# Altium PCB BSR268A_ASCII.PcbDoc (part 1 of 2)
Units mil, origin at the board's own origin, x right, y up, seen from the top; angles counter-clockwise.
Board outline 3689.1 x 2409.61 mil, 4 copper layers (Top Layer, Signal Layer 1, Signal Layer 2, Bottom Layer), stack 60.312 mil thick; 90 components, 29 nets, 160 pads, 335 vias.
Unrouted connection lines stored in the file: 5.
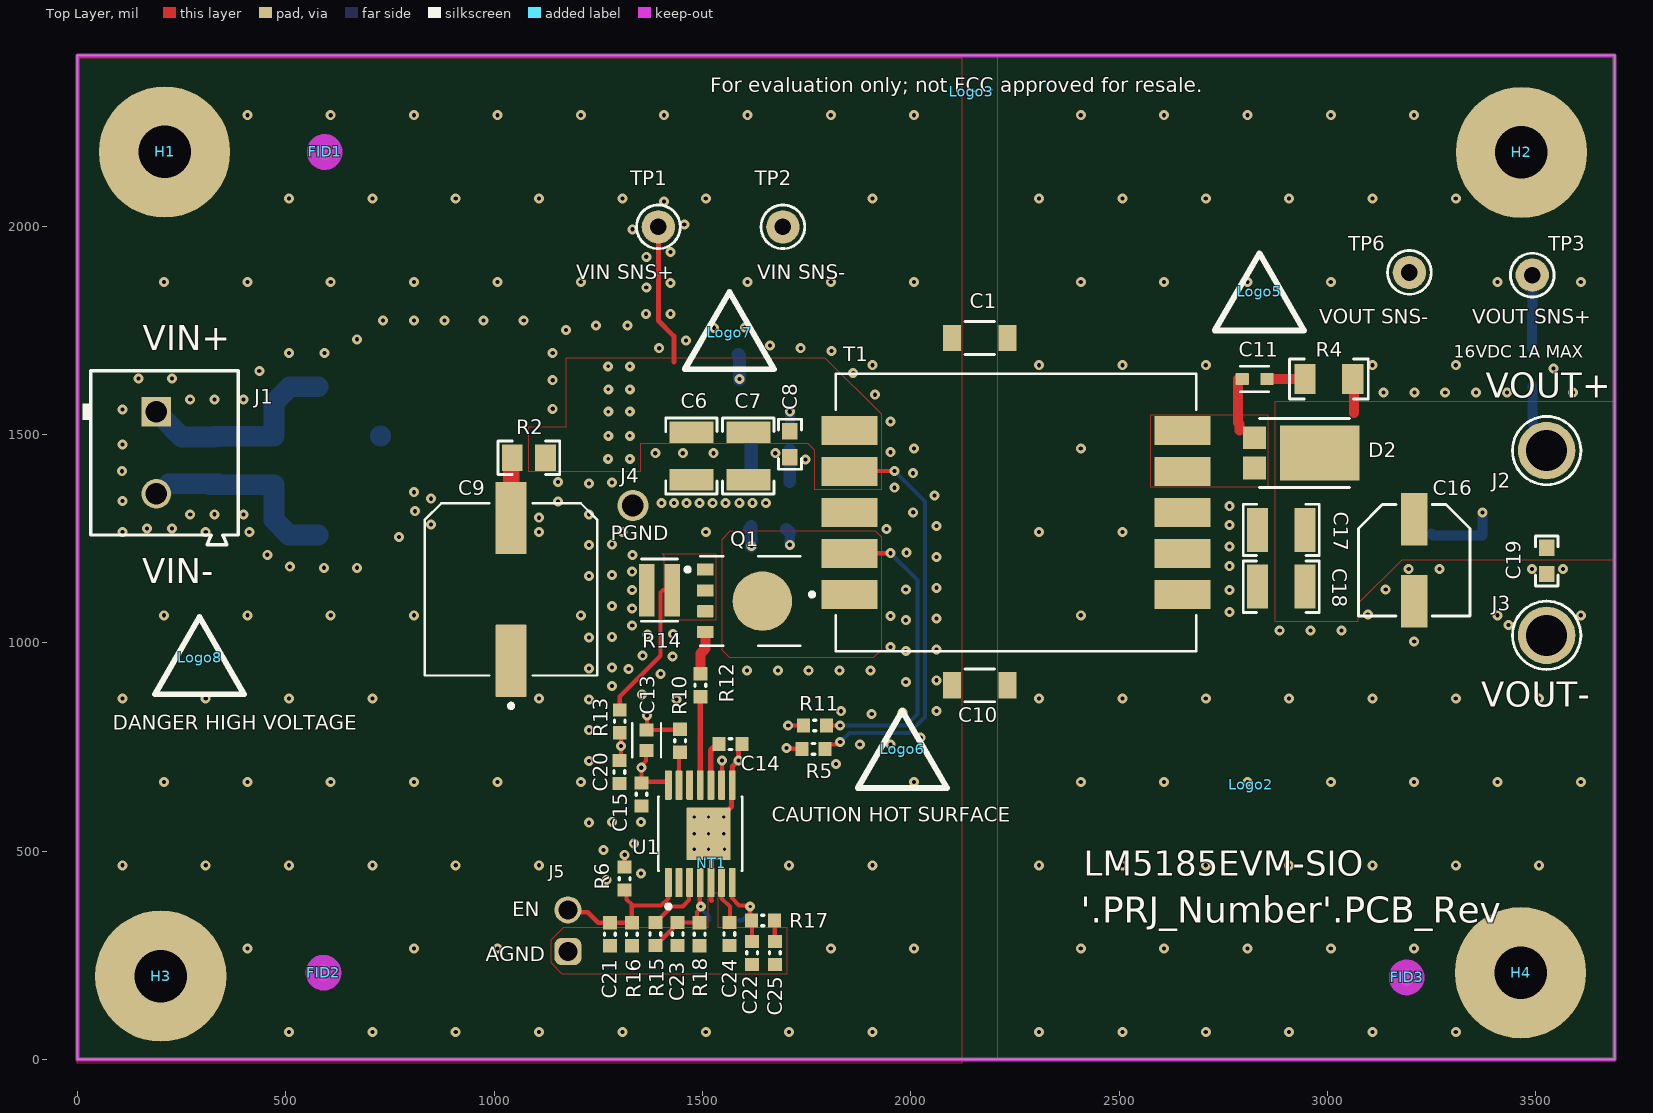
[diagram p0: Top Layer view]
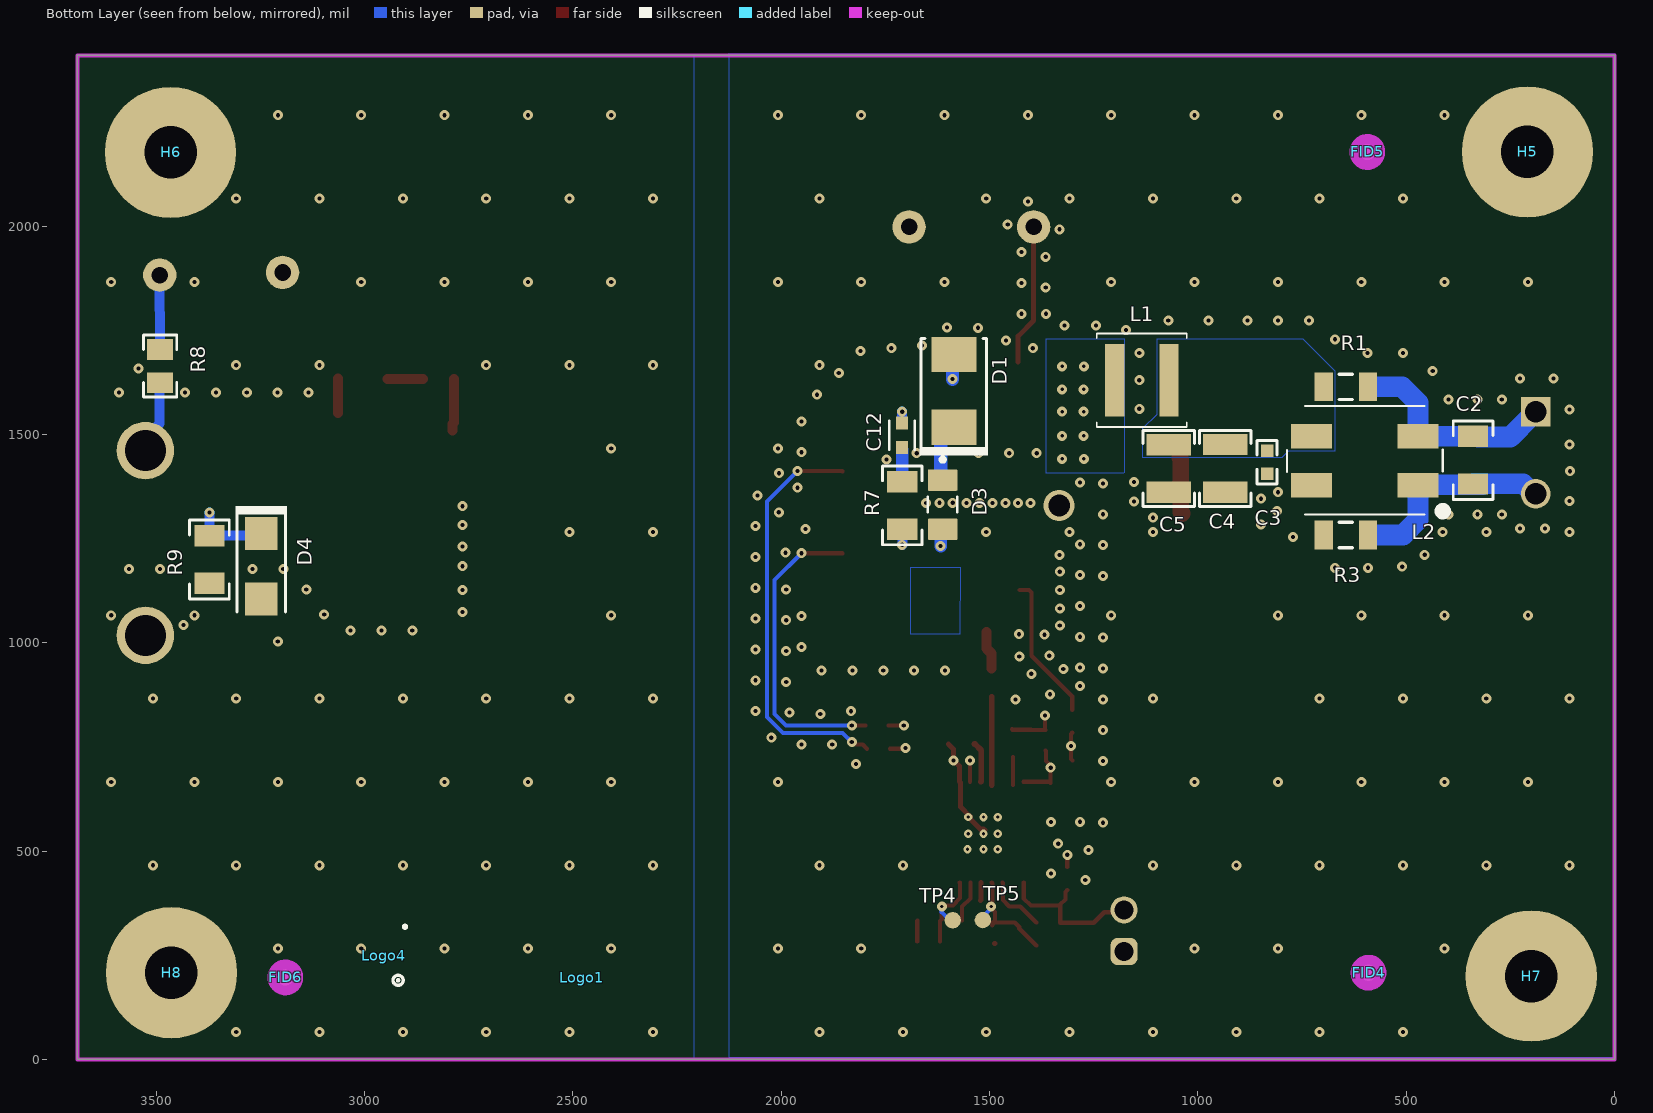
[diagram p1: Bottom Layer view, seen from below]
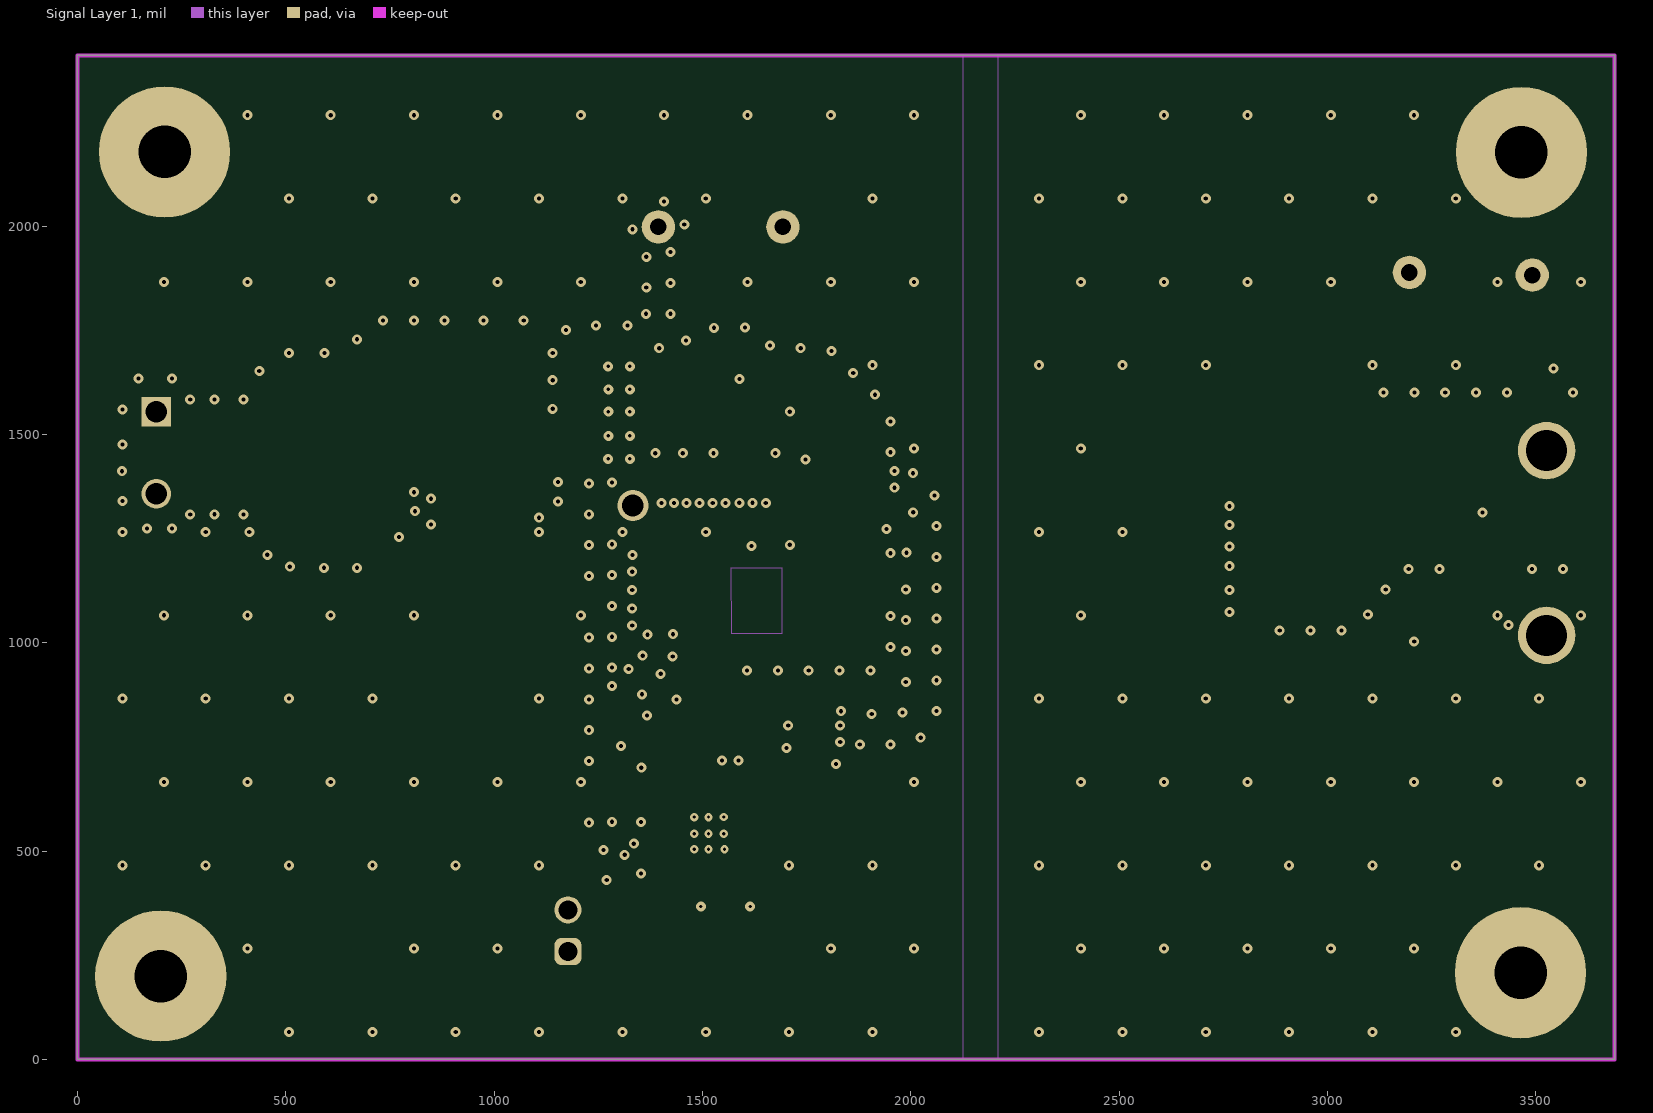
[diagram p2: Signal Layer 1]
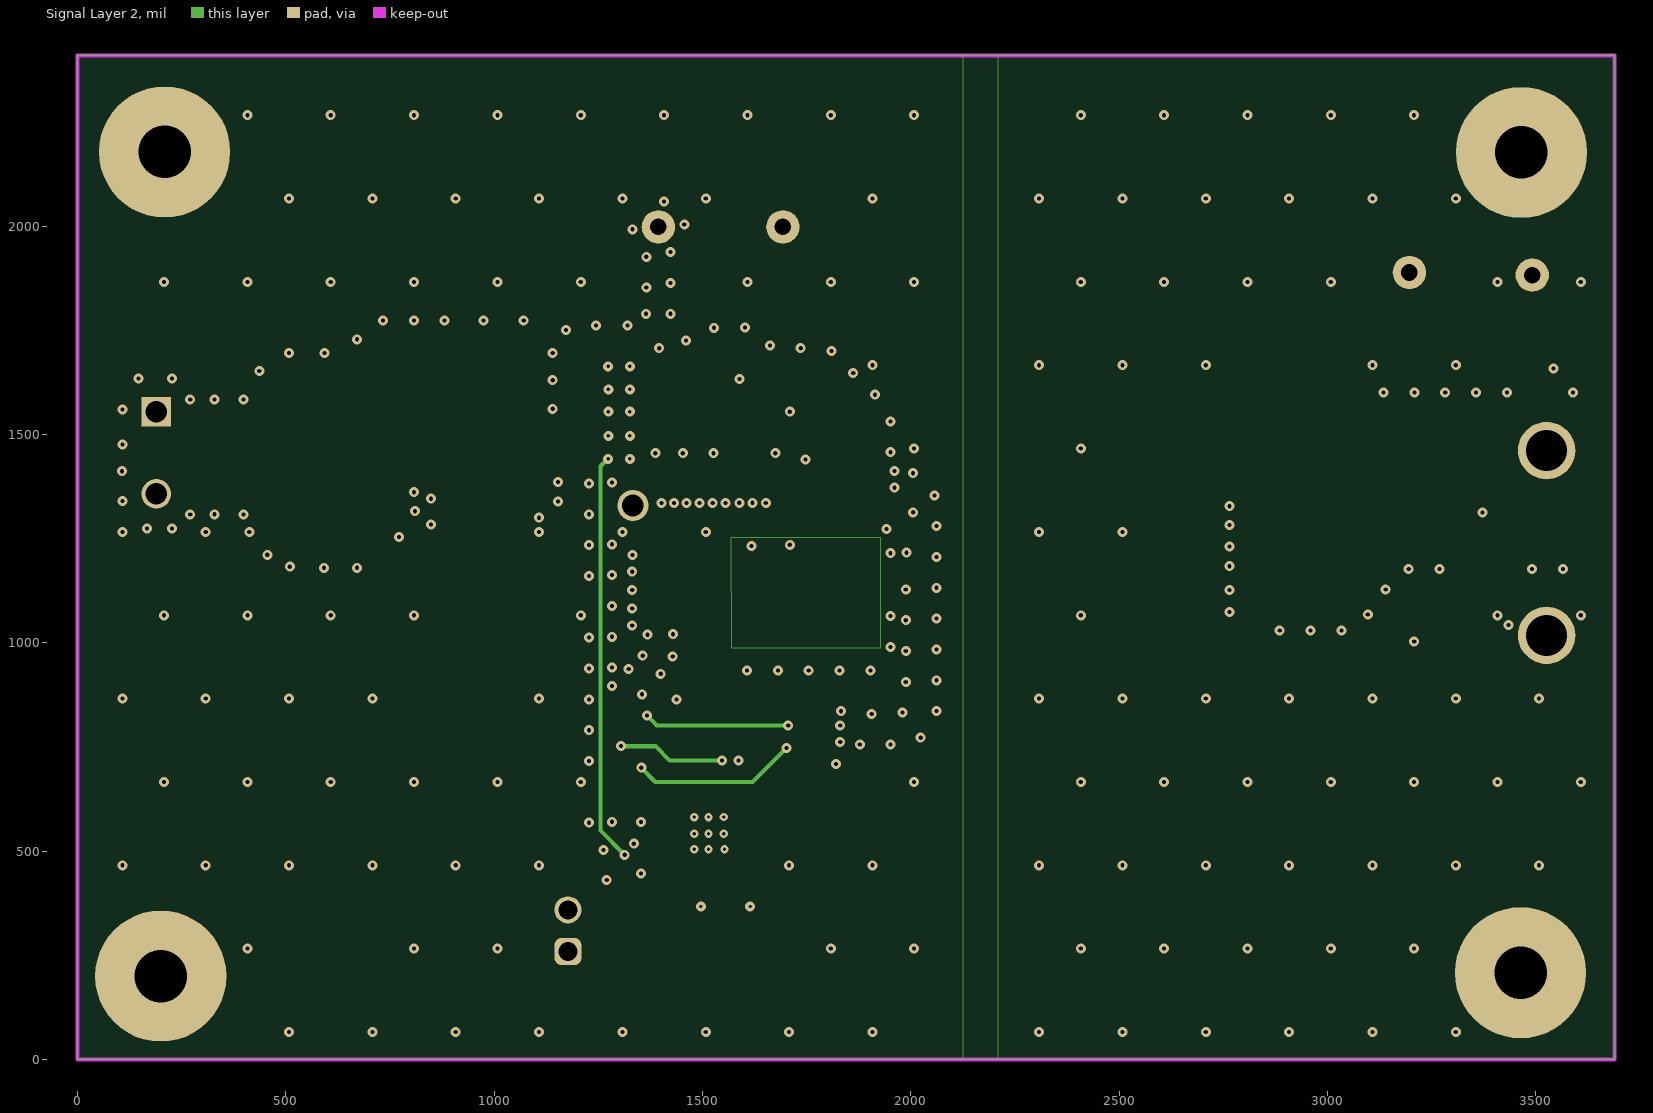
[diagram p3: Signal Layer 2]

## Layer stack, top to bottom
Top Solder: solder mask 0.4, Solder Resist, Dk 3.5
Top Layer: signal copper 2.7559
Dielectric 1: prepreg 8, FR-4 High Tg, Dk 4.1
Signal Layer 1: signal copper 1.4
Dielectric1: core 36, FR-4 High Tg, Dk 4.8
Signal Layer 2: signal copper 1.4
Dielectric 2: prepreg 8, FR-4 High Tg, Dk 4.1
Bottom Layer: signal copper 2.7559
Bottom Solder: solder mask 0.4, Solder Resist, Dk 3.5

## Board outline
0,0 3689.1,0 3689.1,2409.61 0,2409.61

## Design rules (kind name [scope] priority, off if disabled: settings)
AcuteAngle [All] p0: scope1count=1 scope1_0_kind=Board scope1_0_value=Board scope2count=1 scope2_0_kind=Board scope2_0_value=Board commentlength=0 minimum=4.50000000000000E+0001
AcuteAngle [All] p1: minimum=4.50000000000000E+0001 checktracksonly=FALSE
AssemblyTestPointUsage [All] p0: scope1count=1 scope1_0_kind=Board scope1_0_value=Board scope2count=1 scope2_0_kind=Board scope2_0_value=Board commentlength=0
AssemblyTestPointUsage [All] p1: valid=2
AssemblyTestpoint [All] p0: scope1count=1 scope1_0_kind=Board scope1_0_value=Board scope2count=1 scope2_0_kind=Board scope2_0_value=Board commentlength=0
BoardOutlineClearance [All] p0 off: scope1count=1 scope1_0_kind=Board scope1_0_value=Board scope2count=1 scope2_0_kind=Board scope2_0_value=Board commentlength=172 gap=40 // Protel DXP Scope 1 Expression Was: OnCopper and Not InComponentClass('Logo') and not InComponentClass('FiducialMark') and not InRegion(1000,500,4000,800) and not InPoly
BoardOutlineClearance BoardOutlineClearance_Poly [All] p0 off: scope1count=1 scope1_0_kind=Board scope1_0_value=Board scope2count=1 scope2_0_kind=Board scope2_0_value=Board commentlength=58 gap=25 // Protel DXP Scope 1 Expression Was: OnCopper and IsPoly
BoardOutlineClearance BoardOutlineClearance_MountingHoles [All] p0 off: scope1count=1 scope1_0_kind=Board scope1_0_value=Board scope2count=1 scope2_0_kind=Board scope2_0_value=Board commentlength=86 gap=39.37 // Protel DXP Scope 1 Expression Was: OnCopper and InComponentClass('Mounting Holes')
BoardOutlineClearance BoardOutlineClearance_MountingHoles [OnCopper and InComponentClass('Mounting Holes')] p1: gap=39.37 ignorepadtopadclearanceinfootprint=FALSE
BoardOutlineClearance BoardOutlineClearance_Poly [OnCopper and IsPoly] p2: gap=25 ignorepadtopadclearanceinfootprint=FALSE
BoardOutlineClearance [OnCopper and Not InComponentClass('Logo') and not InComponentClass('FiducialMark') and not InRegion(1000,500,4000,800) and not InPoly] p3: gap=40 ignorepadtopadclearanceinfootprint=FALSE
Clearance Clearance_VIN_EMI [All] p0: scope1count=1 scope1_0_kind=NetClass scope1_0_value=EMI_Net scope2count=1 scope2_0_kind=Board scope2_0_value=Board commentlength=0 gap=24
Clearance [All] p0: scope1count=1 scope1_0_kind=Board scope1_0_value=Board scope2count=1 scope2_0_kind=Board scope2_0_value=Board commentlength=0 gap=7.87
Clearance Clearance_FiducialMark [All] p0 off: scope1count=1 scope1_0_kind=Board scope1_0_value=Board scope2count=1 scope2_0_kind=Board scope2_0_value=Board commentlength=81 gap=0 // Protel DXP Scope 2 Expression Was: IsPad and InComponentClass('FiducialMark')
Clearance Clearance_Poly [All] p0 off: scope1count=1 scope1_0_kind=Board scope1_0_value=Board scope2count=1 scope2_0_kind=Board scope2_0_value=Board commentlength=48 gap=10 // Protel DXP Scope 1 Expression Was: InPolygon
Clearance Clearance_Keepouts [All] p0 off: scope1count=1 scope1_0_kind=Board scope1_0_value=Board scope2count=1 scope2_0_kind=Board scope2_0_value=Board commentlength=99 gap=0 // Protel DXP Scope 2 Expression Was: ((IsTrack Or IsArc) And Not InPoly) And IsFree and IsKeepOut
Clearance Clearance_Keepouts [((IsTrack Or IsArc) And Not InPoly) And IsFree and IsKeepOut vs ((IsTrack Or IsArc) And Not InPoly) And IsFree and IsKeepOut] p1: gap=0 ignorepadtopadclearanceinfootprint=FALSE
Clearance Clearance_VIN_EMI [InNetClass('EMI_Net')] p2: gap=24 ignorepadtopadclearanceinfootprint=FALSE
Clearance Clearance_Poly [InPolygon] p3: gap=10 ignorepadtopadclearanceinfootprint=TRUE
Clearance Clearance_FiducialMark [IsKeepOut and InComponentClass('FiducialMark') vs IsPad and InComponentClass('FiducialMark')] p4: gap=0 ignorepadtopadclearanceinfootprint=FALSE
Clearance [All] p5: gap=7.87 ignorepadtopadclearanceinfootprint=TRUE
ComponentClearance "ComponentClearance_CM Choke" [All] p0 off: scope1count=1 scope1_0_kind=Board scope1_0_value=Board scope2count=1 scope2_0_kind=Footprint scope2_0_value=IND_TDK_ACM7060 commentlength=79 gap=0 collisioncheckmode=3 // Protel DXP Scope 1 Expression Was: InComponent('R17') OR InComponent('R18')
ComponentClearance ComponentClearance_NetTie [All] p0: scope1count=1 scope1_0_kind=Footprint scope1_0_value=Net-Tie_10milWide_30milLong scope2count=1 scope2_0_kind=Board scope2_0_value=Board commentlength=0 gap=0 collisioncheckmode=3
ComponentClearance [All] p0: scope1count=1 scope1_0_kind=Board scope1_0_value=Board scope2count=1 scope2_0_kind=Board scope2_0_value=Board commentlength=0 gap=15 collisioncheckmode=3
ComponentClearance ComponentClearance_THtoTH [All] p0 off: scope1count=1 scope1_0_kind=Board scope1_0_value=Board scope2count=1 scope2_0_kind=Board scope2_0_value=Board commentlength=54 gap=20 collisioncheckmode=3 // Protel DXP Scope 2 Expression Was: IsThruComponent
ComponentClearance ComponentClearance_THtoSMT [All] p0 off: scope1count=1 scope1_0_kind=Board scope1_0_value=Board scope2count=1 scope2_0_kind=Board scope2_0_value=Board commentlength=53 gap=30 collisioncheckmode=3 // Protel DXP Scope 2 Expression Was: IsSMTComponent
ComponentClearance ComponentClearance_SmallPassives [All] p0 off: scope1count=1 scope1_0_kind=Board scope1_0_value=Board scope2count=1 scope2_0_kind=Board scope2_0_value=Board commentlength=508 gap=14.96 collisioncheckmode=3 // Protel DXP Scope 2 Expression Was: HasFootprint('0201*') or HasFootprint('0402*') or HasFootprint('0508') or HasFootprint('0603*') or HasFootprint('0612') or HasFootprint('0805*') or HasFootprint('0815*') or HasFootprint('0830*') or HasFootprint('1206*') or HasFootprint('1210*') or HasFootprint('1808*') or HasFootprint('1812*') or HasFootprint('1825*') or HasFootprint('2010*') or HasFootprint('2220*') or HasFootprint('2225*') or HasFootprint('2512*') or HasFootprint('2728*') or HasFootprint('3518*')
ComponentClearance ComponentClearance_MountingHoles [All] p0: scope1count=1 scope1_0_kind=ComponentClass scope1_0_value="Mounting Holes" scope2count=1 scope2_0_kind=Board scope2_0_value=Board commentlength=0 gap=100 collisioncheckmode=3
ComponentClearance ComponentClearance_ScrewToNut [All] p0 off: scope1count=1 scope1_0_kind=Board scope1_0_value=Board scope2count=1 scope2_0_kind=Board scope2_0_value=Board commentlength=71 gap=5 collisioncheckmode=3 // Protel DXP Scope 2 Expression Was: (HasFootprint('Keystone_1902C'))
ComponentClearance ComponentClearance_Logo [All] p0: scope1count=1 scope1_0_kind=ComponentClass scope1_0_value=Logo scope2count=1 scope2_0_kind=Board scope2_0_value=Board commentlength=0 gap=30 collisioncheckmode=3
ComponentClearance ComponentClearance_Shunt [All] p0: scope1count=1 scope1_0_kind=ComponentClass scope1_0_value=Header scope2count=1 scope2_0_kind=ComponentClass scope2_0_value=Shunt commentlength=0 gap=0 collisioncheckmode=3
ComponentClearance ComponentClearance_MountingHoles_FiducialMarks [All] p0: scope1count=1 scope1_0_kind=ComponentClass scope1_0_value="Mounting Holes" scope2count=1 scope2_0_kind=ComponentClass scope2_0_value=FiducialMark commentlength=0 gap=50 collisioncheckmode=3
ComponentClearance ComponentClearance_MountingHoles_FiducialMarks [InComponentClass('Mounting Holes') vs InComponentClass('FiducialMark')] p1: gap=50 collisioncheckmode=3 verticalgap=10 showdistances=FALSE
ComponentClearance ComponentClearance_Shunt [InComponentClass('Header') vs InComponentClass('Shunt')] p2: gap=0 collisioncheckmode=3 verticalgap=0 showdistances=FALSE
ComponentClearance ComponentClearance_Logo [InComponentClass('Logo')] p3: gap=30 collisioncheckmode=3 verticalgap=10 showdistances=FALSE
ComponentClearance ComponentClearance_ScrewToNut [(HasFootprint('NY PMS 440 0025 PH')) vs (HasFootprint('Keystone_1902C'))] p4: gap=5 collisioncheckmode=3 verticalgap=10 showdistances=FALSE
ComponentClearance ComponentClearance_MountingHoles [InComponentClass('Mounting Holes')] p5: gap=100 collisioncheckmode=3 verticalgap=100000 showdistances=FALSE
ComponentClearance ComponentClearance_SmallPassives [HasFootprint('0201*') or HasFootprint('0402*') or HasFootprint('0508') or HasFootprint('0603*') or HasFootprint('0612') or HasFootprint('0805*') or HasFootprint('0815*') or HasFootprint('0830*') or HasFootprint('1206*') or HasFootprint('1210*') or HasFootprint('1808*') or HasFootprint('1812*') or HasFootprint('1825*') or HasFootprint('2010*') or HasFootprint('2220*') or HasFootprint('2225*') or HasFootprint('2512*') or HasFootprint('2728*') or HasFootprint('3518*') vs HasFootprint('0201*') or HasFootprint('0402*') or HasFootprint('0508') or HasFootprint('0603*') or HasFootprint('0612') or HasFootprint('0805*') or HasFootprint('0815*') or HasFootprint('0830*') or HasFootprint('1206*') or HasFootprint('1210*') or HasFootprint('1808*') or HasFootprint('1812*') or HasFootprint('1825*') or HasFootprint('2010*') or HasFootprint('2220*') or HasFootprint('2225*') or HasFootprint('2512*') or HasFootprint('2728*') or HasFootprint('3518*')] p6: gap=14.96 collisioncheckmode=3 verticalgap=10 showdistances=FALSE
ComponentClearance ComponentClearance_THtoSMT [IsThruComponent vs IsSMTComponent] p7: gap=30 collisioncheckmode=3 verticalgap=30 showdistances=FALSE
ComponentClearance ComponentClearance_THtoTH [IsThruComponent vs IsThruComponent] p8: gap=20 collisioncheckmode=3 verticalgap=30 showdistances=FALSE
ComponentClearance ComponentClearance_NetTie [HasFootprint('Net-Tie_10milWide_30milLong')] p9: gap=0 collisioncheckmode=3 verticalgap=0 showdistances=FALSE
ComponentClearance "ComponentClearance_CM Choke" [InComponent('R17') OR InComponent('R18') vs HasFootprint('IND_TDK_ACM7060')] p10: gap=0 collisioncheckmode=3 verticalgap=0 showdistances=FALSE
ComponentClearance [All] p11: gap=15 collisioncheckmode=3 verticalgap=10 showdistances=FALSE
DiffPairsRouting [All] p0: scope1count=1 scope1_0_kind=Board scope1_0_value=Board scope2count=1 scope2_0_kind=Board scope2_0_value=Board commentlength=0
DiffPairsRouting [All] p1: maxlimit=100 minlimit=10 mostfreqgap=10 toplayer_minwidth=15 toplayer_maxwidth=15 toplayer_prefwidth=15 midlayer1_minwidth=15 midlayer1_maxwidth=15 midlayer1_prefwidth=15 midlayer2_minwidth=15 midlayer2_maxwidth=15 midlayer2_prefwidth=15 bottomlayer_minwidth=15 bottomlayer_maxwidth=15 bottomlayer_prefwidth=15 maxuncoupledlength=1000
FabricationTestPointUsage TestPointUsage [All] p0: scope1count=1 scope1_0_kind=Board scope1_0_value=Board scope2count=1 scope2_0_kind=Board scope2_0_value=Board commentlength=0 valid=2 allowmultiple=FALSE
FabricationTestPointUsage TestPointUsage [All] p1: valid=2 allowmultiple=FALSE
FabricationTestpoint Testpoint [All] p0: scope1count=1 scope1_0_kind=Board scope1_0_value=Board scope2count=1 scope2_0_kind=Board scope2_0_value=Board commentlength=0 side=3 testpointundercomponent=TRUE minsize=40 maxsize=100 preferedsize=60 minholesize=0 maxholesize=40 preferedholesize=32 testpointgrid=1
FabricationTestpoint Testpoint [All] p1: side=3 testpointundercomponent=TRUE minsize=40 maxsize=100 preferedsize=60 minholesize=0 maxholesize=40 preferedholesize=32 testpointgrid=1 allowsidetop=TRUE allowsidebottom=TRUE usegrid=TRUE gridtolerance=0.01
FanoutControl Fanout_Small [All] p0 off: scope1count=1 scope1_0_kind=Board scope1_0_value=Board scope2count=1 scope2_0_kind=Board scope2_0_value=Board commentlength=84 // Protel DXP Scope 1 Expression Was: (CompPinCount < 5)   Fanout_Small (Default Rule)
FanoutControl Fanout_Default [All] p0: scope1count=1 scope1_0_kind=Board scope1_0_value=Board scope2count=1 scope2_0_kind=Board scope2_0_value=Board commentlength=30 // Fanout_Default (Default Rule)
FanoutControl Fanout_SOIC [All] p0 off: scope1count=1 scope1_0_kind=Board scope1_0_value=Board scope2count=1 scope2_0_kind=Board scope2_0_value=Board commentlength=71 // Protel DXP Scope 1 Expression Was: IsSOIC   Fanout_SOIC (Default Rule)
FanoutControl Fanout_BGA [All] p0 off: scope1count=1 scope1_0_kind=Board scope1_0_value=Board scope2count=1 scope2_0_kind=Board scope2_0_value=Board commentlength=69 // Protel DXP Scope 1 Expression Was: IsBGA   Fanout_BGA (Default Rule)
FanoutControl Fanout_LCC [All] p0 off: scope1count=1 scope1_0_kind=Board scope1_0_value=Board scope2count=1 scope2_0_kind=Board scope2_0_value=Board commentlength=69 // Protel DXP Scope 1 Expression Was: IsLCC   Fanout_LCC (Default Rule)
FanoutControl Fanout_LCC [IsLCC] p1: bgadir=Out bgaviamode=Centered fanoutstyle=Auto fanoutdirection=Alternating viagrid=1 // Fanout_LCC (Default Rule)
FanoutControl Fanout_BGA [IsBGA] p2: bgadir=Out bgaviamode=Centered fanoutstyle=Auto fanoutdirection=Alternating viagrid=1 // Fanout_BGA (Default Rule)
FanoutControl Fanout_Default [All] p4: bgadir=Out bgaviamode=Centered fanoutstyle=Auto fanoutdirection=Alternating viagrid=1 // Fanout_Default (Default Rule)
FanoutControl Fanout_Small [(CompPinCount < 5)] p5: bgadir=Out bgaviamode=Centered fanoutstyle=Auto fanoutdirection=OutThenIn viagrid=1 // Fanout_Small (Default Rule)
Height [All] p0: scope1count=1 scope1_0_kind=Board scope1_0_value=Board scope2count=1 scope2_0_kind=Board scope2_0_value=Board commentlength=0
HoleSize [All] p0: scope1count=1 scope1_0_kind=Board scope1_0_value=Board scope2count=1 scope2_0_kind=Board scope2_0_value=Board commentlength=0 absolutevalues=TRUE maxlimit=251 minlimit=7.87 maxpercent=80.000 minpercent=20.000
HoleSize [All] p1: absolutevalues=TRUE maxlimit=251 minlimit=7.87 maxpercent=80.000 minpercent=20.000
HoleToHoleClearance [All] p0: scope1count=1 scope1_0_kind=Board scope1_0_value=Board scope2count=1 scope2_0_kind=Board scope2_0_value=Board commentlength=0
LayerPairs [All] p0: scope1count=1 scope1_0_kind=Board scope1_0_value=Board scope2count=1 scope2_0_kind=Board scope2_0_value=Board commentlength=0 enforce=TRUE
MinimumAnnularRing [All] p0: scope1count=1 scope1_0_kind=Board scope1_0_value=Board scope2count=1 scope2_0_kind=Board scope2_0_value=Board commentlength=0 minimumring=6
MinimumAnnularRing MinimumAnnularRing_ThermalPadVias [All] p0 off: scope1count=1 scope1_0_kind=Board scope1_0_value=Board scope2count=1 scope2_0_kind=Board scope2_0_value=Board commentlength=63 minimumring=5.91 // Protel DXP Scope 1 Expression Was: IsVia and InAnyComponent
MinimumAnnularRing MinimumAnnularRing_ThermalPadVias [IsVia and InAnyComponent] p1: minimumring=5.91
MinimumAnnularRing [All] p2: minimumring=6
MinimumSolderMaskSliver [All] p0: scope1count=1 scope1_0_kind=Board scope1_0_value=Board scope2count=1 scope2_0_kind=Board scope2_0_value=Board commentlength=0
MinimumSolderMaskSliver MinimumSolderMaskSliver_Logo [All] p0: scope1count=1 scope1_0_kind=ComponentClass scope1_0_value=Logo scope2count=1 scope2_0_kind=ComponentClass scope2_0_value=Logo commentlength=0
MinimumSolderMaskSliver MinimumSolderMaskSliver_Logo [InComponentClass('Logo') vs InComponentClass('Logo')] p1: minsoldermaskwidth=0.7
MinimumSolderMaskSliver [All] p2: minsoldermaskwidth=3.94
NetAntennae [All] p0: scope1count=1 scope1_0_kind=Board scope1_0_value=Board scope2count=1 scope2_0_kind=Board scope2_0_value=Board commentlength=0
PasteMaskExpansion [All] p0: scope1count=1 scope1_0_kind=Board scope1_0_value=Board scope2count=1 scope2_0_kind=Board scope2_0_value=Board commentlength=0 expansion=0
PlaneClearance [All] p0: scope1count=1 scope1_0_kind=Board scope1_0_value=Board scope2count=1 scope2_0_kind=Board scope2_0_value=Board commentlength=0 clearance=20
PlaneConnect [All] p0: scope1count=1 scope1_0_kind=Board scope1_0_value=Board scope2count=1 scope2_0_kind=Board scope2_0_value=Board commentlength=0 planeconnectstyle=Relief reliefexpansion=10 reliefentries=4 reliefconductorwidth=10 reliefairgap=10
PlaneConnect [All] p1: planeconnectstyle=Relief reliefexpansion=10 reliefentries=4 reliefconductorwidth=10 reliefairgap=10
PolygonConnect [All] p0: scope1count=1 scope1_0_kind=Board scope1_0_value=Board scope2count=1 scope2_0_kind=Board scope2_0_value=Board commentlength=0 connectstyle=Direct reliefconductorwidth=10 reliefentries=4 polygonreliefangle="90 Angle"
PolygonConnect [All] p1: connectstyle=Direct reliefconductorwidth=10 reliefentries=4 polygonreliefangle="90 Angle" airgapwidth=10
RoutingCorners [All] p0: scope1count=1 scope1_0_kind=Board scope1_0_value=Board scope2count=1 scope2_0_kind=Board scope2_0_value=Board commentlength=0 cornerstyle=45-Degree minsetback=100 maxsetback=100
RoutingLayers [All] p0: scope1count=1 scope1_0_kind=Board scope1_0_value=Board scope2count=1 scope2_0_kind=Board scope2_0_value=Board commentlength=0 top layer=Automatic mid layer 1=Automatic mid layer 2=Automatic bottom layer=Automatic
RoutingPriority [All] p0: scope1count=1 scope1_0_kind=Board scope1_0_value=Board scope2count=1 scope2_0_kind=Board scope2_0_value=Board commentlength=0
RoutingTopology [All] p0: scope1count=1 scope1_0_kind=Board scope1_0_value=Board scope2count=1 scope2_0_kind=Board scope2_0_value=Board commentlength=0 topology=Shortest
RoutingVias [All] p0: scope1count=1 scope1_0_kind=Board scope1_0_value=Board scope2count=1 scope2_0_kind=Board scope2_0_value=Board commentlength=0 holewidth=16 width=34 viastyle="Through Hole" minholewidth=7.87 minwidth=20 maxholewidth=40 maxwidth=65
RoutingVias ThermalPadVias [All] p0 off: scope1count=1 scope1_0_kind=Board scope1_0_value=Board scope2count=1 scope2_0_kind=Board scope2_0_value=Board commentlength=63 holewidth=7.87 width=19.68 viastyle="Through Hole" minholewidth=7.87 minwidth=19.68 maxholewidth=12.99 maxwidth=23.62 // Protel DXP Scope 1 Expression Was: IsVia and InAnyComponent
RoutingVias ThermalPadVias [IsVia and InAnyComponent] p1: holewidth=7.87 width=19.68 viastyle="Through Hole" minholewidth=7.87 minwidth=19.68 maxholewidth=12.99 maxwidth=23.62
RoutingVias [All] p2: holewidth=16 width=34 viastyle="Through Hole" minholewidth=7.87 minwidth=20 maxholewidth=40 maxwidth=65
ShortCircuit [All] p0: scope1count=1 scope1_0_kind=Board scope1_0_value=Board scope2count=1 scope2_0_kind=Board scope2_0_value=Board commentlength=0 allowed=FALSE
SilkToBoardRegionClearance [All] p0 off: scope1count=1 scope1_0_kind=Board scope1_0_value=Board scope2count=1 scope2_0_kind=Board scope2_0_value=Board commentlength=130 // Protel DXP Scope 1 Expression Was: Not ((IsComment or IsDesignator) And (Hide <> 'False')) and not InRegion(1000,500,4000,800)
SilkToBoardRegionClearance [Not ((IsComment or IsDesignator) And (Hide <> 'False')) and not InRegion(1000,500,4000,800)] p1:
SilkToSilkClearance [All] p0: scope1count=1 scope1_0_kind=Board scope1_0_value=Board scope2count=1 scope2_0_kind=Board scope2_0_value=Board commentlength=0
SilkToSilkClearance SilkToSilkClearance_Pb-FreeLogo [All] p0 off: scope1count=1 scope1_0_kind=Board scope1_0_value=Board scope2count=1 scope2_0_kind=Board scope2_0_value=Board commentlength=120 // Protel DXP Scope 2 Expression Was: (HasFootprint('Pb-Free_Overlay_Medium') OR HasFootprint('Pb-Free_Overlay_Small'))
SilkToSilkClearance SilkToSilkClearance_Pb-FreeLogo [(HasFootprint('Pb-Free_Overlay_Medium') OR HasFootprint('Pb-Free_Overlay_Small')) vs (HasFootprint('Pb-Free_Overlay_Medium') OR HasFootprint('Pb-Free_Overlay_Small'))] p1: silktosilkclearance=0
SilkToSilkClearance [All] p2: silktosilkclearance=3.94
SilkToSolderMaskClearance "Silk to Solder Mask Opening_TSSOP16" [All] p0: scope1count=1 scope1_0_kind=Footprint scope1_0_value=PWP0016A_N scope2count=1 scope2_0_kind=Board scope2_0_value=Board commentlength=0
SilkToSolderMaskClearance SilkToComponentPadClearance_TSSOP16 [All] p0 off: scope1count=1 scope1_0_kind=Board scope1_0_value=Board scope2count=1 scope2_0_kind=Board scope2_0_value=Board commentlength=100 // Protel DXP Scope 1 Expression Was: (IsPad or IsFill or IsRegion) and  HasFootprint('PWP0016A_N')
SilkToSolderMaskClearance SilkToComponentPadClearance_SOD123 [All] p0 off: scope1count=1 scope1_0_kind=Board scope1_0_value=Board scope2count=1 scope2_0_kind=Board scope2_0_value=Board commentlength=124 // Protel DXP Scope 1 Expression Was: (IsPad or IsFill or IsRegion) and HasFootprint('SOD-123') OR HasFootprint('SOD-123W')
SilkToSolderMaskClearance "Silk to Solder Mask Opening" [All] p0: scope1count=1 scope1_0_kind=Board scope1_0_value=Board scope2count=1 scope2_0_kind=Board scope2_0_value=Board commentlength=0
SilkToSolderMaskClearance SilkToComponentPadClearance [All] p0 off: scope1count=1 scope1_0_kind=Board scope1_0_value=Board scope2count=1 scope2_0_kind=Board scope2_0_value=Board commentlength=87 // Protel DXP Scope 1 Expression Was: (IsPad or IsFill or IsRegion) and InAnycomponent
SilkToSolderMaskClearance SilkToComponentPadClearance_TSSOP16 [(IsPad or IsFill or IsRegion) and  HasFootprint('PWP0016A_N')] p1: minsilkscreentomaskgap=0 clearancetoexposedcopper=TRUE
SilkToSolderMaskClearance SilkToComponentPadClearance_SOD123 [(IsPad or IsFill or IsRegion) and HasFootprint('SOD-123') OR HasFootprint('SOD-123W')] p2: minsilkscreentomaskgap=3 clearancetoexposedcopper=TRUE
SilkToSolderMaskClearance SilkToComponentPadClearance [(IsPad or IsFill or IsRegion) and InAnycomponent] p3: minsilkscreentomaskgap=5 clearancetoexposedcopper=TRUE
SilkToSolderMaskClearance "Silk to Solder Mask Opening_TSSOP16" [HasFootprint('PWP0016A_N')] p4: minsilkscreentomaskgap=0 clearancetoexposedcopper=FALSE
SilkToSolderMaskClearance "Silk to Solder Mask Opening" [All] p5: minsilkscreentomaskgap=3.94 clearancetoexposedcopper=FALSE
SolderMaskExpansion [All] p0: scope1count=1 scope1_0_kind=Board scope1_0_value=Board scope2count=1 scope2_0_kind=Board scope2_0_value=Board commentlength=0 expansion=1.97
SolderMaskExpansion [All] p1: expansion=1.97 istentingtop=FALSE
UnRoutedNet [All] p0: scope1count=1 scope1_0_kind=Board scope1_0_value=Board scope2count=1 scope2_0_kind=Board scope2_0_value=Board commentlength=0
UnRoutedNet [All] p1: checkbadconnections=TRUE
UnpouredPolygon [All] p0: scope1count=1 scope1_0_kind=Board scope1_0_value=Board scope2count=1 scope2_0_kind=Board scope2_0_value=Board commentlength=0
Width [All] p0: scope1count=1 scope1_0_kind=Board scope1_0_value=Board scope2count=1 scope2_0_kind=Board scope2_0_value=Board commentlength=0 maxlimit=100 minlimit=6 preferedwidth=10
Width [All] p1: maxlimit=100 minlimit=6 preferedwidth=10 checkconnectedcopper=TRUE
14 further rules are at their usual default settings.

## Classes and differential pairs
component class Header: J5
net class EMI_Net: NetC2_2 NetC3_1 VIN_EMI
component class "Mounting Holes": H1 H2 H3 H4
component class Logo: Logo2
component class FiducialMark: FID1 FID2 FID3 FID4 FID5 FID6
component class BSR268A_Hardware: !PCB1 FID1 FID2 FID3 FID4 FID5 FID6 H1 H2 H3 H4 H5 H6 H7 H8 Logo1 Logo2 Logo3 Logo4 Logo5 Logo6 Logo7 Logo8 ZZ1 ZZ2 ZZ3 ZZ4
component class AssemblyNote: ZZ1 ZZ2 ZZ3 ZZ4
component class BSR268A_BlankSheet: C1 C2 C3 C4 C5 C6 C7 C8 C9 C10 C11 C12 C13 C14 C15 C16 C17 C18 C19 C20 C21 C22 C23 C24 C25 D1 D2 D3 D4 J1 J2 J3 J4 J5 L1 L2 NT1 Q1 R1 R2 R3 R4 R5 R6 R7 R8 R9 R10 R11 R12 R13 R14 R15 R16 R17 R18 T1 TP1 TP2 TP3 TP4 TP5 TP6 U1

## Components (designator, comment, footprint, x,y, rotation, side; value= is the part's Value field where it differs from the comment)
C1 "202R18W102KV4E" 1206_190 2165.35,1731.3 r180 top
C2 "GRM319R72A104KA01D" 1206 339.68,1438.21 r270 bottom
C3 "GRM188R72A104KA35D" 0603_HV 833.91,1433.34 r270 bottom
C4 "C3225X7S2A475K200AB" 1210_220 934.52,1418.59 r270 bottom
C5 "C3225X7S2A475K200AB" 1210_220 1070.02,1418.47 r270 bottom
C6 "C3225X7S2A475K200AB" 1210_220 1473.69,1447.91 r270 top
C7 "C3225X7S2A475K200AB" 1210_220 1610.38,1447.91 r270 top
C8 "GRM188R72A104KA35D" 0603 1710.03,1476.4 r270 top
C9 "865081757008" FP-865081757008_SMT_CAP_10MM3_10MM3-MFG 1040.7,1128.17 r90 top
C10 "202R18W102KV4E" 1206_190 2165.35,898.01 r180 top
C11 "06031A151JAT2A" FP-06031A151JAT2A_0603-MFG 2825.02,1632.87 r0 top
C12 "06031A151JAT2A" FP-06031A151JAT2A_0603-MFG 1709.93,1498.05 r90 bottom
C13 "06031A101K4T2A" FP-06031A101K4T2A_0603-IPC_C 1365.93,766.18 r270 top
C14 "GRM188Z71C475KE21D" 0603L 1567.39,756.89 r0 top
C15 "GRM188R72A104KA35D" 0603L 1353.84,636.18 r270 top
C16 "EEE-FK1E101XP" SM_RADIAL_D8 3208.17,1197.83 r270 top
C17 "GRM32ER71E226KE15L" 1210_270 2889.02,1270.67 r0 top
C18 "GRM32ER71E226KE15L" 1210_270 2889.02,1134.84 r0 top
C19 "GRM188R72A104KA35D" 0603 3525.97,1196.5 r270 top
C20 "GRM1885C1H101JA01D" 0603L 1300.65,689.98 r270 top
C21 "GCM1885C2A102JA16D" 0603L 1277.82,300.53 r270 top
C22 "CGA3E2NP01H470J080AA" 0603L 1619.2,255.7 r270 top
C23 "C0603C104J4RACTU" 0603L 1440.45,301.13 r90 top
C24 "C0603C104J4RACTU" 0603L 1564.76,301.13 r90 top
C25 "C0603C223K3RACTU" 0603L 1673.65,255.7 r270 top
D1 "SMBJ5362B-TP" SMB 1585.77,1604.69 r90 bottom
D2 "SDT5H100LP5-7" POWERDI5 2903.41,1455.71 r0 top
D3 "ACDBMT1100-HF" FP-ACDBMT1100-HF_SOD-123H-MFG 1612.48,1331.29 r270 bottom
D4 "SMAZ18-13-F" SMA 3248.03,1183.82 r270 bottom
FID1 "Fiducial" Fiducial10-20 593.33,2177.81 r0 top
FID2 "Fiducial" Fiducial10-20 590.55,208.18 r0 top
FID3 "Fiducial" Fiducial10-20 3190,196.85 r0 top
FID4 "Fiducial" Fiducial10-20 590.55,208.18 r180 bottom
FID5 "Fiducial" Fiducial10-20 593.33,2177.81 r180 bottom
FID6 "Fiducial" Fiducial10-20 3190,196.85 r180 bottom
H1 "NY PMS 440 0025 PH" "NY PMS 440 0025 PH" 209.35,2177.81 r0 top locked
H2 "NY PMS 440 0025 PH" "NY PMS 440 0025 PH" 3465.47,2176.67 r0 top locked
H3 "NY PMS 440 0025 PH" "NY PMS 440 0025 PH" 200,200 r0 top locked
H4 "NY PMS 440 0025 PH" "NY PMS 440 0025 PH" 3463.46,208.17 r0 top locked
H5 "1902C" Keystone_1902C 209.35,2177.81 r180 bottom locked
H6 "1902C" Keystone_1902C 3465.47,2176.67 r180 bottom locked
H7 "1902C" Keystone_1902C 200,200 r180 bottom locked
H8 "1902C" Keystone_1902C 3463.46,208.17 r180 bottom locked
J1 "691 101 710 002" Wurth_691101710002 189.35,1455.71 r270 top
J2 "1598-2" Keystone1598-2 3525.97,1461.15 r0 top
J3 "1598-2" Keystone1598-2 3525.97,1017.81 r90 top
J4 "1040" CONN_1040 1333.17,1329.39 r180 top
J5 "61300211121" WURTH_61300211121 1177.2,309.01 r90 top
L1 "XAL5050-223MEB" XAL5050 1134.68,1630.1 r0 bottom
L2 "ACM70V-701-2PL-TL00" IND_TDK_ACM7060 599.51,1436.86 r0 bottom
Logo1 "CE Mark" CE_Mark_5mm 2478.85,195.51 r180 bottom
Logo2 "Texas Instruments" TI_Stacked_Overlay_Small 2816.22,659.45 r0 top
Logo3 "FCC disclaimer" FCC_disclaimer 2145.67,2322.83 r0 top
Logo4 "WEEE logo" WEEE_Minimum 2953.58,248.36 r180 bottom
Logo5 "CAUTION HOT SURFACE" IEC_HotSurface_Small 2836.48,1842.36 r0 top
Logo6 "CAUTION HOT SURFACE" IEC_HotSurface_Small 1979.63,744.09 r0 top
Logo7 "DANGER HIGH VOLTAGE" IEC_HighVoltage_Small 1564.59,1744.2 r0 top
Logo8 "DANGER HIGH VOLTAGE" IEC_HighVoltage_Small 293.25,964.57 r0 top
NT1 "Net-Tie" Net-Tie_10milWide_30milLong 1521.13,470.82 r90 top net-tie
Q1 "NVMFS021N10MCLT1G" FP-NVMFS021N10MCLT1G_DFN5-MFG 1615.02,1100.63 r270 top
R1 "ERJ-8GEY0R00V" 1206L 644.84,1614.21 r0 bottom
R2 "RC0805FR-073R01L" 0805_HV 1083.68,1444.13 r180 top
R3 "ERJ-8GEY0R00V" 1206L 644.84,1258.86 r0 bottom
R4 "ERJ-8ENF1000V" 1206 3003.29,1632.87 r0 top
R5 "RC0603FR-0710RL" 0603L 1766.65,745.51 r0 top
R6 "RC0603FR-07200KL" 0603L 1313.44,434.06 r90 top
R7 "ERJ-8ENF1000V" 1206 1709.68,1329.7 r90 bottom
R8 "ERJ-6GEY0R00V" 0805_HV 3490.72,1664.16 r90 bottom
R9 "ERJ-8ENF3241V" 1206 3372.22,1199.8 r270 bottom
R10 "CRCW0603165KFKEA" 0603L 1446.36,764.82 r90 top
R11 "RC0603JR-071KL" 0603L 1769.86,801.52 r0 top
R12 "RC0603JR-070RL" 0603L 1494.9,898.01 r90 top
R13 "RC0603FR-07100RL" 0603L 1301.53,811.52 r90 top
R14 "PRL1632-R020-F-T1" 0612 1397.15,1126.38 r0 top
R15 "RC0603FR-07294KL" 0603L 1387.05,301.13 r90 top
R16 "RC0603FR-0716K9L" 0603L 1330.51,300.53 r90 top
R17 "RC0603FR-0712K1L" 0603L 1645.11,333.61 r180 top
R18 "RC0603FR-0710KL" 0603L 1493.49,300.53 r90 top
T1 "ZD2250-AE" FP-ZD2250-AE_SMT10_21MM97_16MM9-MFG 2252.57,1312.69 r180 top
TP1 "5000" Keystone5000 1394.22,1998.03 r0 top
TP2 "5001" Keystone5001 1693.14,1998.03 r0 top
TP3 "5000" Keystone5000 3491.48,1882.37 r0 top
TP4 "TP_SM_1MM" TP_SM_1MM 1588.51,334.14 r180 bottom
TP5 "TP_SM_1MM" TP_SM_1MM 1516.1,334.48 r180 bottom
TP6 "5001" Keystone5001 3196.64,1888.78 r0 top
U1 "LM5185-Q1" NEU0014AA-MFG 1494.9,541.34 r90 top
ZZ1 "This Assembly Note is for PCB labels only" AssemblyNoteLabel 185,3938 r0 top
ZZ2 "These assemblies are ESD sensitive, ESD precautions shall be observed." AssemblyNote 185,3829.11 r0 top
ZZ3 "These assemblies must be clean and free from flux and all contaminants. Use of no clean flux is not acceptable." AssemblyNote 185,3740.56 r0 top
ZZ4 "These assemblies must comply with workmanship standards IPC-A-610 Class 2, unless otherwise specified." AssemblyNote 185,3652 r0 top

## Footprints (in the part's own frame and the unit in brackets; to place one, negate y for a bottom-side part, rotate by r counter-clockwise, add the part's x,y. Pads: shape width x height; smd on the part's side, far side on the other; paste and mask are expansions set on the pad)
0603 [mm] "0603 from SM-752 data"
  rect 1x0.95 smd: 1(-0.8,0) 2(0.8,0)
  silkscreen extent -1.52,-0.69 1.52,0.69
0603_HV [mil] "Ernesto recommended land pattern.  26 mil between pads."
  rect 30x30 smd: 1(-28,0) 2(28,0)
  silkscreen extent -52,-24 52,24
0603L [mm] "0603 from SM-752 data"
  rect 0.8x0.85 smd: 1(-0.7,0) 2(0.7,0)
  silkscreen extent -0.07,-0.33 0.07,0.33
0612 [mm] "Panasonic recommended land pattern, fb97d03ed01.pdf dated April 2008"
  rect 0.95x3.2 smd: 1(-0.775,0) 2(0.775,0)
  silkscreen extent -1.1,-1.9 1.1,1.9
0805_HV [mil] "0805 with 30mil clearance between pads"
  rect 50x63 smd: 1(-40,0) 2(40,0)
  silkscreen extent -74,-40 74,40
1206 [mm] "1206 from SM-752 data"
  rect 1.3x1.85 smd: 1(-1.45,0) 2(1.45,0)
  silkscreen extent -2.4,-1.21 2.4,1.21
1206_190 [mm] "1206_190"
  rect 1.1x1.6 smd: 1(-1.7,0) 2(1.7,0)
  silkscreen extent -0.9,-1 0.9,1
1206L [mm] "1206 from SM-752 data"
  rect 1.1x1.75 smd: 1(-1.35,0) 2(1.35,0)
  silkscreen extent -0.4,-0.77 0.4,0.77
1210_220 [mm] "1210"
  rect 1.3x2.7 smd: 1(-1.45,0) 2(1.45,0)
  silkscreen extent -2.32,-1.57 2.32,1.57
1210_270 [mm] "1210"
  rect 1.3x2.7 smd: 1(-1.45,0) 2(1.45,0)
  silkscreen extent -2.32,-1.57 2.32,1.57
AssemblyNote [mil] "Assembly Note"
AssemblyNoteLabel [mil] "Assembly Note for PCB Labels"
CE_Mark_5mm [mil] "Minimum text height for CE Mark"
CONN_1040 [mil] "Test Point, PC  test point Terminal"
  round 75 hole 52: 1(0,0)
FCC_disclaimer [mil]
Fiducial10-20 [mm]
  round 1 smd mask+0: 1(0,0)
  Top Layer keep-out circle w1.178: c0,0 r0.5
FP-06031A101K4T2A_0603-IPC_C [mil]
  rrect12% 31.75x34.18 smd paste+0 mask+0: 1(-24.64,0) 2(24.64,0)
  silkscreen extent -41,-35 41,35
FP-06031A151JAT2A_0603-MFG [mm]
  rrect13% 0.8x0.75 smd paste+0 mask+0: 1(-0.75,0) 2(0.75,0)
  silkscreen extent -0.87,-0.77 0.87,0.77
FP-865081757008_SMT_CAP_10MM3_10MM3-MFG [mm]
  rrect5% 4.4x1.9 smd paste+0 mask+0: 1(-4.35,0) 2(4.35,0)
  silkscreen extent -7.22,-5.25 5.25,5.25
FP-ACDBMT1100-HF_SOD-123H-MFG [mm]
  rrect8% 1.3x1.8 smd paste+0 mask+0: 1(-1.5,0) 2(1.5,0)
  silkscreen extent -2.87,-0.9 0.48,0.9
FP-NVMFS021N10MCLT1G_DFN5-MFG [mm]
  rrect13% 0.75x1 smd paste+0 mask+0: 1(-1.905,-2.748) 2(-0.635,-2.748) 3(0.635,-2.748) 4(1.905,-2.748)
  round 3.631 smd paste+0 mask+0: 5-6(0.021,0.735)
  silkscreen extent -2.73,-3.95 2.73,3.05
FP-ZD2250-AE_SMT10_21MM97_16MM9-MFG [mm]
  rrect6% 3.43x1.79 smd paste+0 mask+0: 1(10.155,5) 2(10.155,2.5) 3(10.155,0) 4(10.155,-2.5) 5(10.155,-5) 6(-10.155,-5) 7(-10.155,-2.5) 8(-10.155,0) 9(-10.155,2.5) 10(-10.155,5)
  silkscreen extent -10.98,-8.45 12.56,8.45
IEC_HighVoltage_Small [mil]
  silkscreen extent -107,-88 107,97
IEC_HotSurface_Small [mil]
  silkscreen extent -107,-93 107,92
IND_TDK_ACM7060 [mm] "TDK Common Mode EMI Filter 7mmx6mm"
  rect 2.5x1.5 smd: 1(-3.25,1.5) 2(-3.25,-1.5) 3(3.25,-1.5) 4(3.25,1.5)
  silkscreen extent -5,-3.32 4.75,3.32
Keystone1598-2 [mm] "Triple Turret"
  round 3.5 hole 2.5: 1(0,0)
  silkscreen extent -2.08,-2.08 2.08,2.08
Keystone5000 [mil] "For Keystone 500x miniature loop terminals"
  round 80 hole 40: 1(0,0)
  silkscreen extent -52,-52 52,52
Keystone5001 [mil] "For Keystone 500x miniature loop terminals"
  round 80 hole 40: 1(0,0)
  silkscreen extent -52,-52 52,52
Keystone_1902C [mil] "Hex Standoff, 4-40 threaded, nylon"
  round 1 on Mech4: 0(0,0)
Net-Tie_10milWide_30milLong [mil] "10mil net tie, no solder mask opening, no solder paste"
  rect 30x10 smd paste-5 mask+0: 1(-15,0) 2(15,0)
NEU0014AA-MFG [mm]
  rrect24% 1.78x0.42 smd paste+0 mask+0: 1(-2.97,1.95) 2(-2.97,1.3) 3(-2.97,0.65) 4(-2.97,0) 5(-2.97,-0.65) 6(-2.97,-1.3) 7(-2.97,-1.95) 8(2.97,-1.95) 9(2.97,-1.3) 10(2.97,-0.65) 11(2.97,0) 12(2.97,0.65) 13(2.97,1.3) 14(2.97,1.95)
  rrect4% 3.2x2.7 smd paste+0 mask+0: 15(0,-0.5)
  silkscreen extent -4.55,-2.55 2.25,2.55
"NY PMS 440 0025 PH" [mm] "4-40 nylon screw and mounting hole"
  round 8 hole 3.2: 1(0,0)
POWERDI5 [mm] "Diodes Inc recommended land pattern, ap02001.pdf rev 60"
  rect 1.4x1.39 smd: 1(-1.991,0.92) 2(-1.991,-0.92)
  rect 4.86x3.36 smd: 3(1.991,0)
  silkscreen extent -1.7,-2.1 3.8,2.1
SM_RADIAL_D8 [mm] "6.3 x 7.7mm:  Panasonic D8"
  rect 3.2x1.6 smd: 1(-2.5,0) 2(2.5,0)
  silkscreen extent -3.4,-3.4 3.4,3.4
SMA [mm] "Molded Diode, 2-Leads, Body 4.3x2.6mm, IPC Medium Density, based on OnSemi component dimensions and land pattern"
  rect 2x2 smd: 1(-2,0) 2(2,0)
  silkscreen extent -3.66,-1.57 2.79,1.57
SMB [mil] "Molded Diode, 2-Leads, Body 5.4x3.6mm, IPC Medium Density, based on OnSemi component dimensions"
  rect 85x107.99 smd: 1(-87.01,0) 2(87.01,0)
  silkscreen extent -155,-82 125,82
TI_Stacked_Overlay_Small [mil]
TP_SM_1MM [mm] "1mm Test Point, SMT"
  round 1 smd paste-0.5: 1(0,0)
WEEE_Minimum [mil] "WEEElie bin"
  silkscreen extent 22,-71 54,74
WURTH_61300211121 [mm] "Header, 2.54mm, 2x1, TH"
  rrect50% 1.65x1.65 hole 1.15: 1(-1.27,0)
  round 1.65 hole 1.15: 2(1.27,0)
Wurth_691101710002 [mm] "Terminal Block, 5 mm, 2x1, TH"
  rect 1.8x1.8 hole 1.3: 1(-2.5,0)
  round 1.8 hole 1.3: 2(2.5,0)
  silkscreen extent -5,-4.5 5.6,5
XAL5050 [mm] "CoilCraft XAL5050 5.28 x 5.48 x 5.1 mm"
  rect 1.18x4.44 smd: 1(-1.655,0) 2(1.655,0)
  silkscreen extent -2.75,-2.85 2.75,2.85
